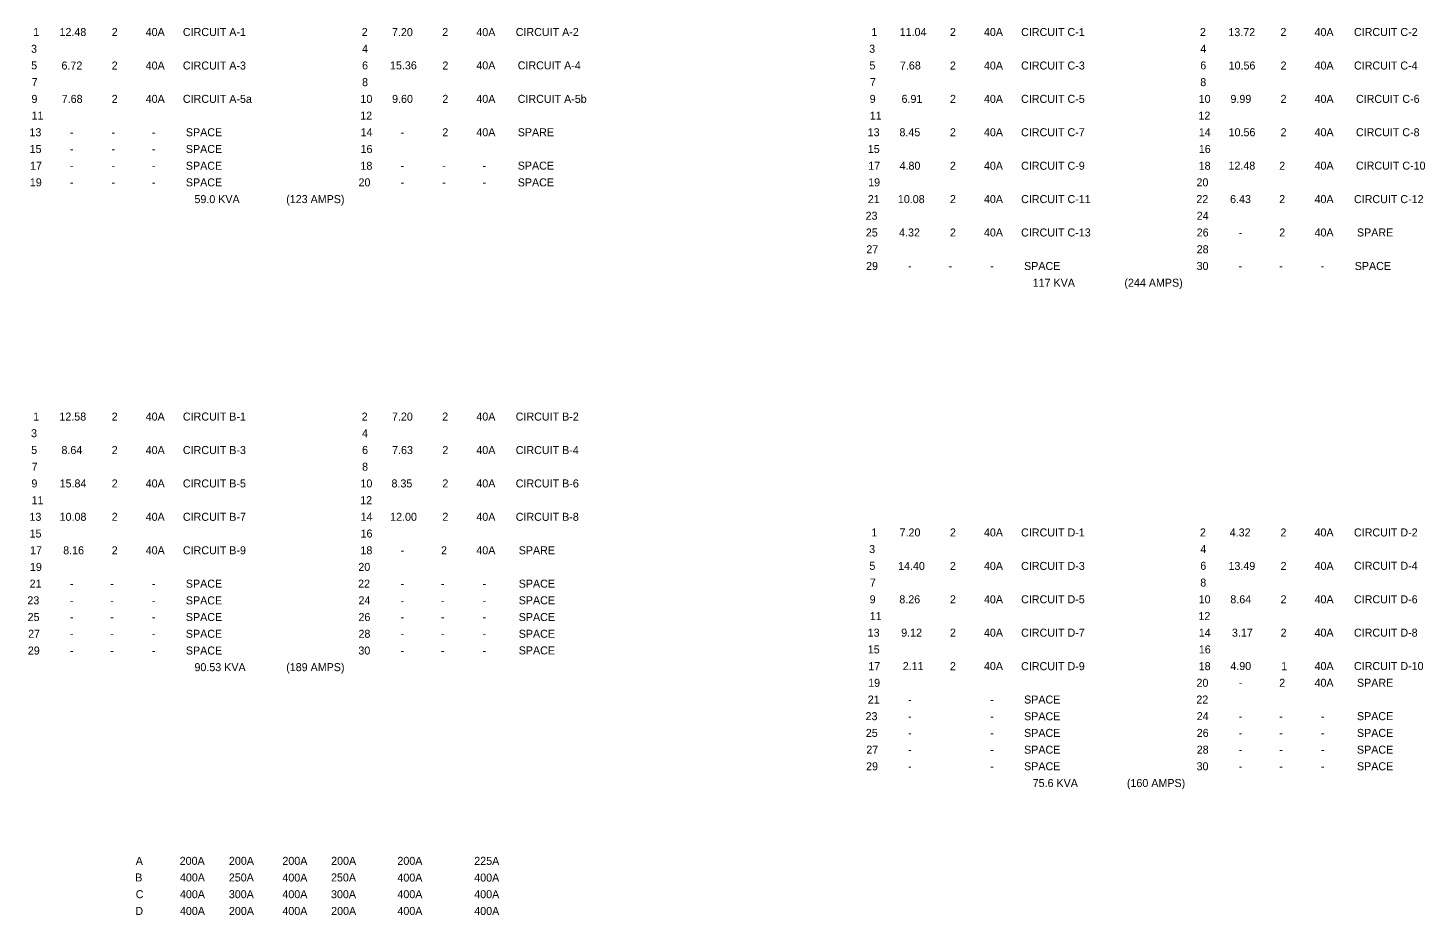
# Model space of a CAD drawing. Extents: x 856079 to 2148480, y 462635 to 2147771.
# Drawn here: x 856079.16 to 856090.51, y 462635.05 to 462642.25 of the extents above; entities that cross this region are included whole.
import ezdxf

# ---------------------------------------------------------------- set-up
doc = ezdxf.new("R2010")
doc.units = 0
doc.layers.add('SheetBorder_dp', color=7, linetype='Continuous')

msp = doc.modelspace()

# ---------------------------------------------------------------- texts
at = {"layer": 'SheetBorder_dp'}
for s, height, p in [('1', 0.065, (856079.204, 462642.187)), ('12.48', 0.065, (856079.418, 462642.187)), ('2', 0.065, (856079.842, 462642.187)), ('40A', 0.065, (856080.118, 462642.187)), ('CIRCUIT A-1', 0.06501, (856080.42, 462642.187)), ('2', 0.065, (856081.872, 462642.187)), ('7.20', 0.065, (856082.118, 462642.186)), ('2', 0.065, (856082.526, 462642.187)), ('40A', 0.065, (856082.803, 462642.186)), ('CIRCUIT A-2', 0.06501, (856083.123, 462642.187)), ('1', 0.065, (856086.011, 462642.187)), ('11.04', 0.065, (856086.241, 462642.187)), ('2', 0.065, (856086.649, 462642.187)), ('40A', 0.065, (856086.925, 462642.187)), ('CIRCUIT C-1', 0.06501, (856087.227, 462642.187)), ('2', 0.065, (856088.679, 462642.187)), ('13.72', 0.065, (856088.91, 462642.186)), ('2', 0.065, (856089.333, 462642.187)), ('40A', 0.065, (856089.61, 462642.186)), ('CIRCUIT C-2', 0.06501, (856089.93, 462642.187)), ('3', 0.065, (856079.187, 462642.051)), ('4', 0.065, (856081.875, 462642.051)), ('3', 0.065, (856085.993, 462642.051)), ('4', 0.065, (856088.682, 462642.051)), ('5', 0.065, (856079.188, 462641.916)), ('6.72', 0.065, (856079.434, 462641.915)), ('2', 0.065, (856079.842, 462641.915)), ('40A', 0.065, (856080.118, 462641.915)), ('CIRCUIT A-3', 0.06501, (856080.42, 462641.915)), ('6', 0.065, (856081.875, 462641.916)), ('15.36', 0.065, (856082.102, 462641.916)), ('2', 0.065, (856082.527, 462641.915)), ('40A', 0.065, (856082.803, 462641.916)), ('CIRCUIT A-4', 0.06501, (856083.139, 462641.916)), ('5', 0.065, (856085.995, 462641.916)), ('7.68', 0.065, (856086.243, 462641.915)), ('2', 0.065, (856086.649, 462641.915)), ('40A', 0.065, (856086.925, 462641.915)), ('CIRCUIT C-3', 0.06501, (856087.227, 462641.915)), ('6', 0.065, (856088.682, 462641.916)), ('10.56', 0.065, (856088.912, 462641.915)), ('2', 0.065, (856089.334, 462641.915)), ('40A', 0.065, (856089.61, 462641.915)), ('CIRCUIT C-4', 0.06501, (856089.93, 462641.915)), ('7', 0.065, (856079.192, 462641.78)), ('8', 0.065, (856081.875, 462641.78)), ('7', 0.065, (856085.999, 462641.78)), ('8', 0.065, (856088.682, 462641.78)), ('9', 0.065, (856079.19, 462641.644)), ('7.68', 0.065, (856079.436, 462641.644)), ('2', 0.065, (856079.842, 462641.644)), ('40A', 0.065, (856080.118, 462641.644)), ('CIRCUIT A-5a', 0.06501, (856080.42, 462641.644)), ('10', 0.065, (856081.862, 462641.644)), ('9.60', 0.065, (856082.119, 462641.644)), ('2', 0.065, (856082.527, 462641.644)), ('40A', 0.065, (856082.803, 462641.644)), ('CIRCUIT A-5b', 0.06501, (856083.139, 462641.644)), ('9', 0.065, (856085.997, 462641.644)), ('6.91', 0.065, (856086.256, 462641.644)), ('2', 0.065, (856086.649, 462641.644)), ('40A', 0.065, (856086.925, 462641.644)), ('CIRCUIT C-5', 0.06501, (856087.227, 462641.644)), ('10', 0.065, (856088.669, 462641.644)), ('9.99', 0.065, (856088.927, 462641.644)), ('2', 0.065, (856089.334, 462641.644)), ('40A', 0.065, (856089.61, 462641.644)), ('CIRCUIT C-6', 0.06501, (856089.946, 462641.644)), ('11', 0.065, (856079.191, 462641.508)), ('12', 0.065, (856081.86, 462641.508)), ('11', 0.065, (856085.998, 462641.508)), ('12', 0.065, (856088.667, 462641.508)), ('13', 0.065, (856079.174, 462641.373)), ('-', 0.065, (856079.502, 462641.373)), ('-', 0.065, (856079.841, 462641.373)), ('-', 0.065, (856080.169, 462641.373)), (' SPACE', 0.065, (856080.42, 462641.373)), ('14', 0.065, (856081.863, 462641.373)), ('-', 0.065, (856082.187, 462641.373)), ('2', 0.065, (856082.527, 462641.373)), ('40A', 0.065, (856082.803, 462641.373)), ('SPARE', 0.065, (856083.139, 462641.373)), ('13', 0.065, (856085.981, 462641.373)), ('8.45', 0.065, (856086.239, 462641.373)), ('2', 0.065, (856086.649, 462641.373)), ('40A', 0.065, (856086.925, 462641.373)), ('CIRCUIT C-7', 0.06501, (856087.227, 462641.373)), ('14', 0.065, (856088.67, 462641.373)), ('10.56', 0.065, (856088.912, 462641.373)), ('2', 0.065, (856089.334, 462641.373)), ('40A', 0.065, (856089.61, 462641.373)), ('CIRCUIT C-8', 0.06501, (856089.946, 462641.373)), ('15', 0.065, (856079.175, 462641.237)), (' SPACE', 0.065, (856080.42, 462641.237)), ('16', 0.065, (856081.863, 462641.237)), ('15', 0.065, (856085.982, 462641.237)), ('16', 0.065, (856088.67, 462641.237)), ('17', 0.065, (856079.179, 462641.101)), ('-', 0.065, (856079.502, 462641.237)), ('-', 0.065, (856079.841, 462641.237)), ('-', 0.065, (856080.169, 462641.237)), (' SPACE', 0.065, (856080.42, 462641.101)), ('18', 0.065, (856081.862, 462641.101)), ('SPACE', 0.065, (856083.139, 462641.102)), ('17', 0.065, (856085.986, 462641.101)), ('4.80', 0.065, (856086.24, 462641.101)), ('2', 0.065, (856086.649, 462641.101)), ('40A', 0.065, (856086.925, 462641.101)), ('CIRCUIT C-9', 0.06501, (856087.227, 462641.101)), ('18', 0.065, (856088.669, 462641.101)), ('12.48', 0.065, (856088.911, 462641.102)), ('2', 0.065, (856089.323, 462641.101)), ('40A', 0.065, (856089.61, 462641.102)), ('CIRCUIT C-10', 0.06501, (856089.946, 462641.102)), ('-', 0.065, (856079.502, 462641.101)), ('-', 0.065, (856079.841, 462641.101)), ('-', 0.065, (856080.169, 462641.101)), ('-', 0.065, (856082.187, 462641.102)), ('-', 0.065, (856082.525, 462641.101)), ('-', 0.065, (856082.854, 462641.102)), ('19', 0.065, (856079.177, 462640.966)), ('-', 0.065, (856079.502, 462640.966)), ('-', 0.065, (856079.841, 462640.966)), ('-', 0.065, (856080.169, 462640.966)), (' SPACE', 0.065, (856080.42, 462640.966)), ('20', 0.065, (856081.846, 462640.966)), ('-', 0.065, (856082.187, 462640.966)), ('-', 0.065, (856082.525, 462640.966)), ('-', 0.065, (856082.854, 462640.966)), ('SPACE', 0.065, (856083.139, 462640.966)), ('19', 0.065, (856085.985, 462640.966)), ('20', 0.065, (856088.651, 462640.966)), ('59.0 KVA', 0.065, (856080.514, 462640.83)), ('(123 AMPS)', 0.065, (856081.259, 462640.83)), ('21', 0.065, (856085.982, 462640.83)), ('10.08', 0.065, (856086.226, 462640.83)), ('2', 0.065, (856086.649, 462640.83)), ('40A', 0.065, (856086.925, 462640.83)), ('CIRCUIT C-11', 0.06501, (856087.227, 462640.83)), ('22', 0.065, (856088.65, 462640.83)), ('6.43', 0.065, (856088.924, 462640.83)), ('2', 0.065, (856089.323, 462640.83)), ('40A', 0.065, (856089.61, 462640.83)), ('CIRCUIT C-12', 0.06501, (856089.93, 462640.83)), ('23', 0.065, (856085.964, 462640.695)), ('24', 0.065, (856088.653, 462640.695)), ('25', 0.065, (856085.966, 462640.559)), ('4.32', 0.065, (856086.236, 462640.559)), ('2', 0.065, (856086.649, 462640.559)), ('40A', 0.065, (856086.925, 462640.559)), ('CIRCUIT C-13', 0.06501, (856087.227, 462640.559)), ('26', 0.065, (856088.653, 462640.559)), ('2', 0.065, (856089.323, 462640.559)), ('40A', 0.065, (856089.61, 462640.559)), (' SPARE', 0.065, (856089.93, 462640.559)), ('27', 0.065, (856085.97, 462640.423)), ('28', 0.065, (856088.653, 462640.423)), ('-', 0.065, (856088.994, 462640.559)), ('29', 0.065, (856085.968, 462640.287)), ('-', 0.065, (856086.309, 462640.287)), ('-', 0.065, (856086.637, 462640.287)), ('-', 0.065, (856086.976, 462640.287)), (' SPACE', 0.065, (856087.227, 462640.287)), ('30', 0.065, (856088.652, 462640.287)), ('-', 0.065, (856088.993, 462640.287)), ('-', 0.065, (856089.322, 462640.287)), ('-', 0.065, (856089.66, 462640.287)), (' SPACE', 0.065, (856089.912, 462640.287)), ('117 KVA', 0.065, (856087.321, 462640.151)), ('(244 AMPS)', 0.065, (856088.066, 462640.151)), ('1', 0.065, (856079.204, 462639.064)), ('12.58', 0.065, (856079.417, 462639.064)), ('2', 0.065, (856079.842, 462639.064)), ('40A', 0.065, (856080.118, 462639.064)), ('CIRCUIT B-1', 0.06501, (856080.42, 462639.064)), ('2', 0.065, (856081.872, 462639.064)), ('7.20', 0.065, (856082.118, 462639.064)), ('2', 0.065, (856082.526, 462639.064)), ('40A', 0.065, (856082.803, 462639.064)), ('CIRCUIT B-2', 0.06501, (856083.123, 462639.064)), ('3', 0.065, (856079.187, 462638.929)), ('4', 0.065, (856081.875, 462638.929)), ('5', 0.065, (856079.188, 462638.793)), ('8.64', 0.065, (856079.434, 462638.792)), ('2', 0.065, (856079.842, 462638.792)), ('40A', 0.065, (856080.118, 462638.792)), ('CIRCUIT B-3', 0.06501, (856080.42, 462638.792)), ('6', 0.065, (856081.875, 462638.793)), ('7.63', 0.065, (856082.119, 462638.792)), ('2', 0.065, (856082.527, 462638.792)), ('40A', 0.065, (856082.803, 462638.792)), ('CIRCUIT B-4', 0.06501, (856083.123, 462638.792)), ('7', 0.065, (856079.192, 462638.657)), ('8', 0.065, (856081.875, 462638.657)), ('9', 0.065, (856079.19, 462638.521)), ('15.84', 0.065, (856079.419, 462638.521)), ('2', 0.065, (856079.842, 462638.521)), ('40A', 0.065, (856080.118, 462638.521)), ('CIRCUIT B-5', 0.06501, (856080.42, 462638.521)), ('10', 0.065, (856081.862, 462638.521)), ('8.35', 0.065, (856082.114, 462638.521)), ('2', 0.065, (856082.527, 462638.521)), ('40A', 0.065, (856082.803, 462638.521)), ('CIRCUIT B-6', 0.06501, (856083.123, 462638.521)), ('11', 0.065, (856079.191, 462638.385)), ('12', 0.065, (856081.86, 462638.385)), ('13', 0.065, (856079.174, 462638.25)), ('10.08', 0.065, (856079.419, 462638.25)), ('2', 0.065, (856079.842, 462638.25)), ('40A', 0.065, (856080.118, 462638.25)), ('CIRCUIT B-7', 0.06501, (856080.42, 462638.25)), ('14', 0.065, (856081.863, 462638.25)), ('12.00', 0.065, (856082.103, 462638.25)), ('2', 0.065, (856082.527, 462638.25)), ('40A', 0.065, (856082.803, 462638.25)), ('CIRCUIT B-8', 0.06501, (856083.123, 462638.25)), ('15', 0.065, (856079.175, 462638.114)), ('16', 0.065, (856081.863, 462638.114)), ('1', 0.065, (856086.011, 462638.123)), ('7.20', 0.065, (856086.24, 462638.123)), ('2', 0.065, (856086.649, 462638.123)), ('40A', 0.065, (856086.925, 462638.123)), ('CIRCUIT D-1', 0.06501, (856087.227, 462638.123)), ('2', 0.065, (856088.679, 462638.123)), ('4.32', 0.065, (856088.921, 462638.123)), ('2', 0.065, (856089.333, 462638.123)), ('40A', 0.065, (856089.61, 462638.123)), ('CIRCUIT D-2', 0.06501, (856089.93, 462638.123)), ('17', 0.065, (856079.179, 462637.978)), ('8.16', 0.065, (856079.448, 462637.978)), ('2', 0.065, (856079.842, 462637.978)), ('40A', 0.065, (856080.118, 462637.978)), ('CIRCUIT B-9', 0.06501, (856080.42, 462637.978)), ('18', 0.065, (856081.862, 462637.978)), ('-', 0.065, (856082.187, 462637.978)), ('2', 0.065, (856082.516, 462637.978)), ('40A', 0.065, (856082.803, 462637.978)), (' SPARE', 0.065, (856083.123, 462637.978)), ('3', 0.065, (856085.993, 462637.988)), ('4', 0.065, (856088.682, 462637.988)), ('19', 0.065, (856079.178, 462637.843)), ('20', 0.065, (856081.845, 462637.843)), ('5', 0.065, (856085.995, 462637.852)), ('14.40', 0.065, (856086.228, 462637.851)), ('2', 0.065, (856086.649, 462637.851)), ('40A', 0.065, (856086.925, 462637.851)), ('CIRCUIT D-3', 0.06501, (856087.227, 462637.851)), ('6', 0.065, (856088.682, 462637.852)), ('13.49', 0.065, (856088.911, 462637.851)), ('2', 0.065, (856089.334, 462637.851)), ('40A', 0.065, (856089.61, 462637.851)), ('CIRCUIT D-4', 0.06501, (856089.93, 462637.852)), ('21', 0.065, (856079.175, 462637.707)), (' SPACE', 0.065, (856080.42, 462637.707)), ('22', 0.065, (856081.843, 462637.707)), (' SPACE', 0.065, (856083.123, 462637.707)), ('7', 0.065, (856085.999, 462637.716)), ('8', 0.065, (856088.682, 462637.716)), ('-', 0.065, (856079.502, 462637.707)), ('-', 0.065, (856079.83, 462637.707)), ('-', 0.065, (856080.169, 462637.707)), ('-', 0.065, (856082.187, 462637.707)), ('-', 0.065, (856082.515, 462637.707)), ('-', 0.065, (856082.854, 462637.707)), ('9', 0.065, (856085.997, 462637.58)), ('8.26', 0.065, (856086.238, 462637.58)), ('2', 0.065, (856086.649, 462637.58)), ('40A', 0.065, (856086.925, 462637.58)), ('CIRCUIT D-5', 0.06501, (856087.227, 462637.58)), ('10', 0.065, (856088.669, 462637.58)), ('8.64', 0.065, (856088.926, 462637.58)), ('2', 0.065, (856089.334, 462637.58)), ('40A', 0.065, (856089.61, 462637.58)), ('CIRCUIT D-6', 0.06501, (856089.93, 462637.58)), ('23', 0.065, (856079.157, 462637.572)), ('-', 0.065, (856079.502, 462637.571)), ('-', 0.065, (856079.83, 462637.571)), ('-', 0.065, (856080.169, 462637.571)), (' SPACE', 0.065, (856080.42, 462637.571)), ('24', 0.065, (856081.846, 462637.572)), ('-', 0.065, (856082.187, 462637.571)), ('-', 0.065, (856082.515, 462637.571)), ('-', 0.065, (856082.854, 462637.571)), (' SPACE', 0.065, (856083.123, 462637.572)), ('25', 0.065, (856079.159, 462637.436)), ('-', 0.065, (856079.502, 462637.436)), ('-', 0.065, (856079.83, 462637.436)), ('-', 0.065, (856080.169, 462637.436)), (' SPACE', 0.065, (856080.42, 462637.436)), ('26', 0.065, (856081.846, 462637.436)), ('-', 0.065, (856082.187, 462637.436)), ('-', 0.065, (856082.515, 462637.436)), ('-', 0.065, (856082.854, 462637.436)), (' SPACE', 0.065, (856083.123, 462637.436)), ('11', 0.065, (856085.998, 462637.444)), ('12', 0.065, (856088.667, 462637.444)), ('27', 0.065, (856079.163, 462637.3)), ('-', 0.065, (856079.502, 462637.3)), ('-', 0.065, (856079.83, 462637.3)), ('-', 0.065, (856080.169, 462637.3)), (' SPACE', 0.065, (856080.42, 462637.3)), ('28', 0.065, (856081.846, 462637.3)), ('-', 0.065, (856082.187, 462637.3)), ('-', 0.065, (856082.515, 462637.3)), ('-', 0.065, (856082.854, 462637.3)), (' SPACE', 0.065, (856083.123, 462637.3)), ('13', 0.065, (856085.981, 462637.309)), ('9.12', 0.065, (856086.253, 462637.309)), ('2', 0.065, (856086.649, 462637.309)), ('40A', 0.065, (856086.925, 462637.309)), ('CIRCUIT D-7', 0.06501, (856087.227, 462637.309)), ('14', 0.065, (856088.67, 462637.309)), ('3.17', 0.065, (856088.939, 462637.309)), ('2', 0.065, (856089.334, 462637.309)), ('40A', 0.065, (856089.61, 462637.309)), ('CIRCUIT D-8', 0.06501, (856089.93, 462637.309)), ('29', 0.065, (856079.161, 462637.164)), ('-', 0.065, (856079.502, 462637.164)), ('-', 0.065, (856079.83, 462637.164)), ('-', 0.065, (856080.169, 462637.164)), (' SPACE', 0.065, (856080.42, 462637.164)), ('30', 0.065, (856081.845, 462637.164)), ('-', 0.065, (856082.187, 462637.164)), ('-', 0.065, (856082.515, 462637.164)), ('-', 0.065, (856082.854, 462637.164)), (' SPACE', 0.065, (856083.123, 462637.165)), ('15', 0.065, (856085.982, 462637.173)), ('16', 0.065, (856088.67, 462637.173)), ('90.53 KVA', 0.065, (856080.514, 462637.029)), ('(189 AMPS)', 0.065, (856081.259, 462637.029)), ('17', 0.065, (856085.986, 462637.037)), ('2.11', 0.065, (856086.266, 462637.038)), ('2', 0.065, (856086.649, 462637.037)), ('40A', 0.065, (856086.925, 462637.038)), ('CIRCUIT D-9', 0.06501, (856087.227, 462637.037)), ('18', 0.065, (856088.669, 462637.037)), ('4.90', 0.065, (856088.926, 462637.038)), ('1', 0.065, (856089.339, 462637.037)), ('40A', 0.065, (856089.61, 462637.038)), ('CIRCUIT D-10', 0.06501, (856089.93, 462637.038)), ('19', 0.065, (856085.985, 462636.902)), ('20', 0.065, (856088.651, 462636.902)), ('2', 0.065, (856089.323, 462636.902)), ('40A', 0.065, (856089.61, 462636.902)), (' SPARE', 0.065, (856089.93, 462636.902)), ('-', 0.065, (856088.994, 462636.902)), ('21', 0.065, (856085.982, 462636.766)), ('-', 0.065, (856086.309, 462636.766)), ('-', 0.065, (856086.976, 462636.766)), (' SPACE', 0.065, (856087.227, 462636.766)), ('22', 0.065, (856088.65, 462636.766)), ('23', 0.065, (856085.964, 462636.631)), ('-', 0.065, (856086.309, 462636.631)), ('-', 0.065, (856086.976, 462636.631)), (' SPACE', 0.065, (856087.227, 462636.63)), ('24', 0.065, (856088.653, 462636.631)), ('-', 0.065, (856088.994, 462636.631)), ('-', 0.065, (856089.322, 462636.631)), ('-', 0.065, (856089.322, 462636.631)), ('-', 0.065, (856089.661, 462636.631)), (' SPACE', 0.065, (856089.93, 462636.631)), ('25', 0.065, (856085.966, 462636.495)), ('-', 0.065, (856086.309, 462636.495)), ('-', 0.065, (856086.976, 462636.495)), (' SPACE', 0.065, (856087.227, 462636.495)), ('26', 0.065, (856088.653, 462636.495)), ('-', 0.065, (856088.994, 462636.495)), ('-', 0.065, (856089.322, 462636.495)), ('-', 0.065, (856089.322, 462636.495)), ('-', 0.065, (856089.661, 462636.495)), (' SPACE', 0.065, (856089.93, 462636.495)), ('27', 0.065, (856085.97, 462636.359)), (' SPACE', 0.065, (856087.227, 462636.359)), ('28', 0.065, (856088.653, 462636.359)), (' SPACE', 0.065, (856089.93, 462636.359)), ('29', 0.065, (856085.968, 462636.224)), ('-', 0.065, (856086.309, 462636.359)), ('-', 0.065, (856086.976, 462636.359)), (' SPACE', 0.065, (856087.227, 462636.224)), ('30', 0.065, (856088.652, 462636.224)), ('-', 0.065, (856088.994, 462636.359)), ('-', 0.065, (856089.322, 462636.359)), ('-', 0.065, (856089.322, 462636.359)), ('-', 0.065, (856089.661, 462636.359)), (' SPACE', 0.065, (856089.93, 462636.224)), ('-', 0.065, (856086.309, 462636.224)), ('-', 0.065, (856086.976, 462636.224)), ('-', 0.065, (856088.994, 462636.224)), ('-', 0.065, (856089.322, 462636.224)), ('-', 0.065, (856089.661, 462636.224)), ('75.6 KVA', 0.065, (856087.321, 462636.088)), ('(160 AMPS)', 0.065, (856088.086, 462636.088)), ('A', 0.065, (856080.037, 462635.456)), ('200A', 0.065, (856080.394, 462635.456)), ('200A', 0.065, (856080.794, 462635.456)), ('200A', 0.065, (856081.228, 462635.456)), ('200A', 0.065, (856081.624, 462635.456)), ('200A', 0.065, (856082.162, 462635.456)), ('225A', 0.065, (856082.786, 462635.456)), ('B', 0.065, (856080.033, 462635.321)), ('400A', 0.065, (856080.396, 462635.321)), ('250A', 0.065, (856080.793, 462635.321)), ('400A', 0.065, (856081.228, 462635.32)), ('250A', 0.065, (856081.623, 462635.321)), ('400A', 0.065, (856082.162, 462635.32)), ('400A', 0.065, (856082.786, 462635.32)), ('C', 0.065, (856080.037, 462635.185)), ('400A', 0.065, (856080.396, 462635.185)), ('300A', 0.065, (856080.793, 462635.185)), ('400A', 0.065, (856081.228, 462635.185)), ('300A', 0.065, (856081.623, 462635.185)), ('400A', 0.065, (856082.162, 462635.185)), ('400A', 0.065, (856082.786, 462635.185)), ('D', 0.065, (856080.034, 462635.049)), ('400A', 0.065, (856080.396, 462635.049)), ('200A', 0.065, (856080.794, 462635.049)), ('400A', 0.065, (856081.228, 462635.049)), ('200A', 0.065, (856081.624, 462635.049)), ('400A', 0.065, (856082.162, 462635.049)), ('400A', 0.065, (856082.786, 462635.049))]:
    msp.add_text(s, height=height, rotation=0, dxfattribs=at).set_placement(p)

doc.saveas('drawing.dxf')
